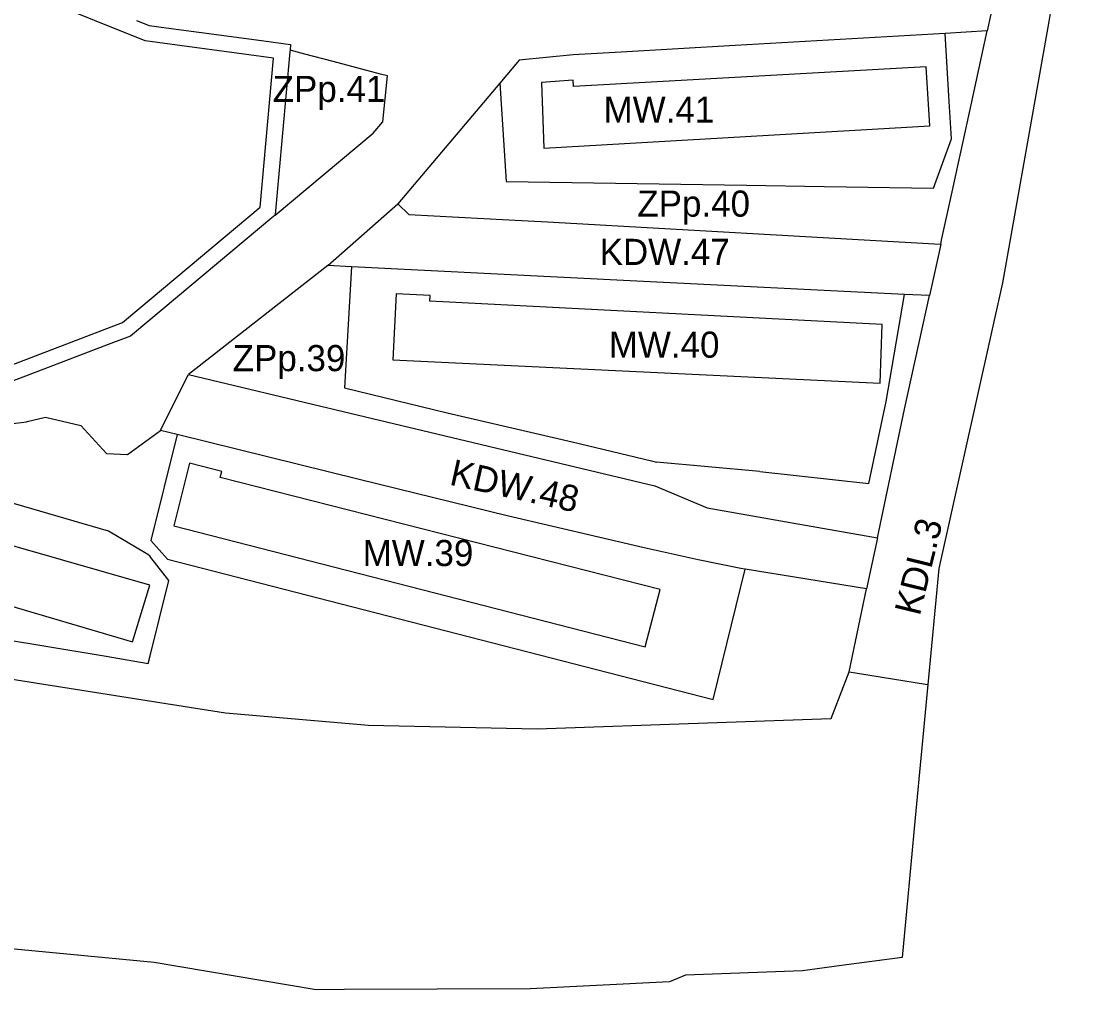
# Model space of a CAD drawing. Extents: x 7424434 to 7425898, y 5541432 to 5542659.
# Drawn here: x 7425520.4 to 7425724.5, y 5541432.1 to 5541617.4 of the extents above; entities that cross this region are included whole.
import ezdxf

# ---------------------------------------------------------------- set-up
doc = ezdxf.new("R2010")
doc.units = 0
for name, color, linetype in [('linie rozgraniczające', 7, 'Continuous'), ('nieprzekraczalne linie zabudowy', 7, 'Continuous'), ('obowiazujace linie zabudowy', 7, 'Continuous'), ('przeznaczenia terenów', 7, 'Continuous')]:
    doc.layers.add(name, color=color, linetype=linetype)

msp = doc.modelspace()

# ---------------------------------------------------------------- linework, layer by layer
at = {"layer": 'linie rozgraniczające'}
for p, q in [((7425724.48, 5541665.9), (7425717.08, 5541617.4)), ((7425706.91, 5541623.36), (7425705.24, 5541615.6)), ((7425542.47, 5541617.59), (7425544.88, 5541616.62)), ((7425717.08, 5541617.4), (7425708.2, 5541567.38)), ((7425544.88, 5541616.62), (7425548.13, 5541616.18)), ((7425548.13, 5541616.18), (7425554.37, 5541615.35)), ((7425554.37, 5541615.35), (7425560.6, 5541614.51)), ((7425705.24, 5541615.6), (7425697.18, 5541615.13)), ((7425702.19, 5541601.47), (7425705.24, 5541615.6)), ((7425560.6, 5541614.51), (7425566.84, 5541613.67)), ((7425566.84, 5541613.67), (7425571.94, 5541612.99)), ((7425697.18, 5541615.13), (7425657, 5541612.8)), ((7425697.99, 5541602.1), (7425697.18, 5541615.13)), ((7425571.81, 5541611.58), (7425571.11, 5541603.8)), ((7425571.84, 5541611.93), (7425571.81, 5541611.58)), ((7425571.94, 5541612.99), (7425571.84, 5541611.93)), ((7425574.64, 5541611.16), (7425571.84, 5541611.93)), ((7425580.07, 5541609.73), (7425574.64, 5541611.16)), ((7425635.19, 5541611.51), (7425626.03, 5541610.99)), ((7425657, 5541612.8), (7425635.19, 5541611.51)), ((7425589.12, 5541607.34), (7425580.07, 5541609.73)), ((7425615.7, 5541609.97), (7425612, 5541605.6)), ((7425626.03, 5541610.99), (7425615.7, 5541609.97)), ((7425590.46, 5541606.99), (7425589.12, 5541607.34)), ((7425589.56, 5541598.2), (7425590.46, 5541606.99)), ((7425612, 5541605.6), (7425592.45, 5541582.48)), ((7425612, 5541605.6), (7425613.21, 5541586.79)), ((7425571.11, 5541603.8), (7425570.41, 5541596.03)), ((7425698.44, 5541594.94), (7425697.99, 5541602.1)), ((7425698.09, 5541582.74), (7425702.19, 5541601.47)), ((7425587.73, 5541596.03), (7425589.56, 5541598.2)), ((7425568.99, 5541580.36), (7425587.73, 5541596.03)), ((7425570.41, 5541596.03), (7425569.7, 5541588.26)), ((7425694.95, 5541585.48), (7425698.44, 5541594.94)), ((7425569.7, 5541588.26), (7425569, 5541580.48)), ((7425613.21, 5541586.79), (7425659.19, 5541586.1)), ((7425659.19, 5541586.1), (7425674.06, 5541585.84)), ((7425674.06, 5541585.84), (7425694.95, 5541585.48)), ((7425696.59, 5541575.87), (7425698.09, 5541582.74)), ((7425579.09, 5541570.68), (7425592.45, 5541582.48)), ((7425592.45, 5541582.48), (7425594.58, 5541580.49)), ((7425568.32, 5541579.8), (7425544.79, 5541560.12)), ((7425568.99, 5541580.36), (7425568.32, 5541579.8)), ((7425569, 5541580.48), (7425568.99, 5541580.36)), ((7425594.58, 5541580.49), (7425613.68, 5541579.44)), ((7425613.68, 5541579.44), (7425621.12, 5541579.03)), ((7425621.12, 5541579.03), (7425695.2, 5541574.84)), ((7425695.2, 5541574.84), (7425696.35, 5541574.77)), ((7425696.35, 5541574.77), (7425695.84, 5541572.4)), ((7425696.35, 5541574.77), (7425696.59, 5541575.87)), ((7425695.84, 5541572.4), (7425694.2, 5541564.94)), ((7425579.09, 5541570.68), (7425552.37, 5541549.85)), ((7425583.57, 5541570.42), (7425579.09, 5541570.68)), ((7425583.57, 5541570.42), (7425582.28, 5541547.28)), ((7425638.17, 5541567.7), (7425583.57, 5541570.42)), ((7425689.44, 5541565.17), (7425638.17, 5541567.7)), ((7425708.2, 5541567.38), (7425696, 5541512.73)), ((7425685.93, 5541544.68), (7425689.44, 5541565.17)), ((7425694.2, 5541564.94), (7425689.44, 5541565.17)), ((7425689.45, 5541543.18), (7425694.2, 5541564.94)), ((7425544.79, 5541560.12), (7425541.3, 5541557.2)), ((7425541.3, 5541557.2), (7425537.01, 5541555.56)), ((7425537.01, 5541555.56), (7425525.56, 5541551.18)), ((7425525.56, 5541551.18), (7425518.53, 5541548.49)), ((7425549.48, 5541544.04), (7425552.37, 5541549.85)), ((7425552.37, 5541549.85), (7425582.03, 5541542.76)), ((7425582.28, 5541547.28), (7425601.9, 5541542.53)), ((7425547.04, 5541539.13), (7425549.48, 5541544.04)), ((7425682.61, 5541528.97), (7425685.93, 5541544.68)), ((7425582.03, 5541542.76), (7425641.63, 5541528.52)), ((7425601.9, 5541542.53), (7425625.84, 5541536.98)), ((7425684.24, 5541518.56), (7425689.45, 5541543.18)), ((7425518.78, 5541540.45), (7425521.37, 5541540.81)), ((7425521.37, 5541540.81), (7425521.52, 5541540.83)), ((7425521.52, 5541540.83), (7425525.06, 5541541.65)), ((7425525.06, 5541541.65), (7425531.8, 5541540.09)), ((7425531.8, 5541540.09), (7425536.7, 5541534.75)), ((7425537.07, 5541519.86), (7425469.17, 5541539.63)), ((7425540.71, 5541534.52), (7425547.04, 5541539.13)), ((7425550.21, 5541538.35), (7425545.2, 5541518.08)), ((7425550.21, 5541538.35), (7425547.04, 5541539.13)), ((7425585.04, 5541529.77), (7425550.21, 5541538.35)), ((7425625.84, 5541536.98), (7425640.98, 5541533.31)), ((7425536.7, 5541534.75), (7425540.71, 5541534.52)), ((7425640.98, 5541533.31), (7425641.97, 5541533.09)), ((7425661.74, 5541531.28), (7425641.97, 5541533.09)), ((7425613.39, 5541522.78), (7425585.04, 5541529.77)), ((7425661.74, 5541531.28), (7425682.61, 5541528.97)), ((7425641.63, 5541528.52), (7425651.69, 5541524.32)), ((7425651.69, 5541524.32), (7425665.79, 5541521.83)), ((7425639.62, 5541516.67), (7425613.39, 5541522.78)), ((7425665.79, 5541521.83), (7425684.24, 5541518.56)), ((7425544.3, 5541515.57), (7425537.07, 5541519.86)), ((7425545.2, 5541518.08), (7425548.39, 5541514.5)), ((7425684.24, 5541518.56), (7425683.26, 5541513.89)), ((7425544.98, 5541515.17), (7425544.3, 5541515.57)), ((7425649.97, 5541514.39), (7425639.62, 5541516.67)), ((7425545.22, 5541514.85), (7425544.98, 5541515.17)), ((7425548.63, 5541510.4), (7425545.22, 5541514.85)), ((7425548.39, 5541514.5), (7425652.82, 5541487.67)), ((7425658.08, 5541512.72), (7425649.97, 5541514.39)), ((7425683.26, 5541513.89), (7425682.18, 5541508.8)), ((7425652.82, 5541487.67), (7425658.91, 5541512.59)), ((7425658.91, 5541512.59), (7425658.08, 5541512.72)), ((7425682.18, 5541508.8), (7425658.91, 5541512.59)), ((7425696, 5541512.73), (7425693.9, 5541490.5)), ((7425545.04, 5541495.97), (7425548.63, 5541510.4)), ((7425456.75, 5541509), (7425536.63, 5541495.96)), ((7425678.83, 5541492.95), (7425682.18, 5541508.8)), ((7425536.63, 5541495.96), (7425544.68, 5541494.53)), ((7425544.68, 5541494.53), (7425545.04, 5541495.97)), ((7425499.02, 5541494.66), (7425545.68, 5541487.28)), ((7425675.39, 5541484), (7425678.83, 5541492.95)), ((7425678.83, 5541492.95), (7425687.12, 5541491.61)), ((7425687.12, 5541491.61), (7425693.45, 5541490.58)), ((7425693.9, 5541490.5), (7425691.49, 5541465)), ((7425693.45, 5541490.58), (7425693.9, 5541490.51)), ((7425545.68, 5541487.28), (7425559.46, 5541485.1)), ((7425559.46, 5541485.1), (7425586.87, 5541482.71)), ((7425586.87, 5541482.71), (7425619.13, 5541482.02)), ((7425619.13, 5541482.02), (7425651.72, 5541483.17)), ((7425651.72, 5541483.17), (7425675.39, 5541484)), ((7425691.49, 5541465), (7425689.81, 5541447.13)), ((7425689.81, 5541447.13), (7425688.97, 5541438.29)), ((7425545.85, 5541437.34), (7425517.75, 5541439.97)), ((7425688.97, 5541438.29), (7425677.39, 5541436.73)), ((7425576.85, 5541432.11), (7425545.85, 5541437.34)), ((7425669.92, 5541435.71), (7425647.51, 5541434.87)), ((7425677.39, 5541436.73), (7425669.92, 5541435.71)), ((7425644.45, 5541433.6), (7425617.79, 5541432.28)), ((7425647.51, 5541434.87), (7425644.45, 5541433.6)), ((7425582.22, 5541432.12), (7425576.85, 5541432.11)), ((7425617.79, 5541432.28), (7425582.22, 5541432.12))]:
    msp.add_line(p, q, dxfattribs=at)
at = {"layer": 'nieprzekraczalne linie zabudowy'}
msp.add_lwpolyline([(7425516.21, 5541550.81), (7425539.76, 5541559.82), (7425542.87, 5541562.42), (7425566.11, 5541581.87), (7425568.69, 5541610.4), (7425544.11, 5541613.7), (7425524.39, 5541621.67), (7425514.3, 5541626.75), (7425462.65, 5541652.8), (7425423.35, 5541666), (7425404.27, 5541669.87), (7425401.75, 5541646.75), (7425399.07, 5541622.15), (7425398.91, 5541620.78), (7425392.88, 5541565.32), (7425432.43, 5541559.06), (7425432.38, 5541558.61), (7425444.12, 5541557.2), (7425463.89, 5541554.08), (7425469.74, 5541553.7)], close=True, dxfattribs=at)
at = {"layer": 'obowiazujace linie zabudowy'}
for points in [[(7425620.41, 5541593.17), (7425694.28, 5541597.43), (7425693.57, 5541608.73), (7425626.11, 5541604.94), (7425626.04, 5541606.2), (7425619.93, 5541605.75)], [(7425591.49, 5541552.66), (7425684.8, 5541548.17), (7425685.18, 5541559.41), (7425598.57, 5541563.87), (7425598.62, 5541564.93), (7425592.15, 5541565.26)], [(7425470.94, 5541519.51), (7425541.67, 5541498.71), (7425545.01, 5541509.52), (7425477.34, 5541528.93), (7425477.64, 5541529.96), (7425471.45, 5541531.73), (7425468.39, 5541520.26)], [(7425552.58, 5541532.86), (7425549.56, 5541520.91), (7425639.81, 5541497.72), (7425642.67, 5541508.72), (7425558.49, 5541530.14), (7425558.78, 5541531.28)]]:
    msp.add_lwpolyline(points, close=True, dxfattribs=at)

# ---------------------------------------------------------------- texts
at = {"layer": 'przeznaczenia terenów'}
for s, p in [('ZPp.41', (7425568.51, 5541602)), ('MW.41', (7425631.84, 5541598.04)), ('ZPp.40', (7425638.3, 5541580.05)), ('KDW.47', (7425631.09, 5541570.81)), ('MW.40', (7425632.84, 5541553.05)), ('ZPp.39', (7425560.86, 5541550.48)), ('MW.39', (7425585.73, 5541513.18))]:
    msp.add_text(s, height=5, dxfattribs=at).set_placement(p)
for s, rotation, p in [('KDW.48', 347.5254, (7425602.16, 5541528.79)), ('KDL.3', 76.2803, (7425692.33, 5541503.49))]:
    msp.add_text(s, height=5, rotation=rotation, dxfattribs=at).set_placement(p)

doc.saveas('drawing.dxf')
